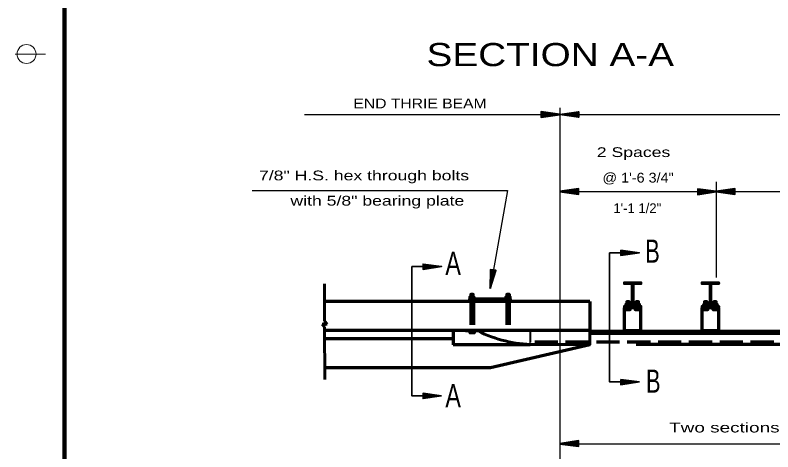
# Model space of a CAD drawing. Extents: x 856.9 to 891.7, y -2278.5 to -2254.7.
# Drawn here: x 858.05 to 868.03, y -2268.1 to -2262.35 of the extents above; entities that cross this region are included whole.
import ezdxf
from ezdxf.enums import TextEntityAlignment as Align

# ---------------------------------------------------------------- set-up
doc = ezdxf.new("R2010")
doc.units = 0
doc.header["$LTSCALE"] = 0.051
doc.linetypes.add('LONG_DASHED', pattern=[7.5, 6, -1.5])
doc.layers.add('1', color=7, linetype='Continuous', lineweight=70)
doc.layers.add('3', color=7, linetype='Continuous', lineweight=40)

msp = doc.modelspace()

# ---------------------------------------------------------------- linework, layer by layer
at = {"layer": '1', "lineweight": 25}
for p, q in [((865.22225, -2263.57275), (865.22225, -2272.82167)), ((861.86167, -2263.65783), (865.22225, -2263.65783)), ((865.22225, -2263.65783), (877.422, -2263.65783)), ((867.282, -2264.5455), (867.282, -2265.80808)), ((865.22225, -2264.67633), (877.5155, -2264.67633)), ((864.82975, -2266.6885), (864.82975, -2266.50583)), ((865.22225, -2267.99842), (873.72275, -2267.99842))]:
    msp.add_line(p, q, dxfattribs=at)
at = {"layer": '1', "lineweight": 60}
for p, q in [((862.1255, -2265.89133), (862.1255, -2266.38442)), ((864.02033, -2266.08983), (864.587, -2266.08983)), ((862.157, -2266.42175), (862.09342, -2266.42392)), ((862.09342, -2266.42392), (862.1255, -2266.45933)), ((862.1255, -2266.38442), (862.157, -2266.42175)), ((862.1255, -2266.45933), (862.12683, -2267.1535)), ((862.12625, -2266.50508), (865.61775, -2266.50508)), ((863.98108, -2266.51092), (864.14475, -2266.51092))]:
    msp.add_line(p, q, dxfattribs=at)
at = {"layer": '1'}
for p, q in [((865.61775, -2266.12317), (862.1255, -2266.12317)), ((865.61775, -2266.12317), (865.61775, -2266.50508)), ((866.07233, -2266.51742), (866.07233, -2266.20767)), ((866.29092, -2266.51742), (866.29092, -2266.20767)), ((867.09592, -2266.51742), (867.09592, -2266.20767)), ((867.31417, -2266.51742), (867.31417, -2266.20767)), ((865.61775, -2266.50508), (862.12625, -2266.50508)), ((863.81658, -2266.50508), (863.81658, -2266.69625)), ((882.07667, -2266.51742), (865.61517, -2266.51742)), ((873.06783, -2266.545), (865.61842, -2266.545)), ((863.81658, -2266.6145), (862.12625, -2266.6145)), ((864.83383, -2266.69625), (863.81658, -2266.69625)), ((865.61775, -2266.69625), (864.30783, -2266.99625)), ((882.68767, -2266.68917), (866.22875, -2266.68917)), ((864.30783, -2266.99625), (862.12625, -2266.99625))]:
    msp.add_line(p, q, dxfattribs=at)
at = {"layer": '1', "lineweight": 13}
for p, q in [((864.02033, -2266.08983), (864.02033, -2266.11992)), ((864.587, -2266.08983), (864.587, -2266.12117))]:
    msp.add_line(p, q, dxfattribs=at)
at = {"layer": '1', "linetype": 'LONG_DASHED'}
for p, q in [((864.04917, -2266.12317), (864.04917, -2266.50967)), ((864.08383, -2266.12317), (864.08383, -2266.50433)), ((873.72408, -2266.65825), (864.84167, -2266.65825))]:
    msp.add_line(p, q, dxfattribs=at)
at = {"layer": '1', "linetype": 'LONG_DASHED', "lineweight": 60}
for p, q in [((864.52333, -2266.12317), (864.52333, -2266.50633)), ((864.55875, -2266.12317), (864.55875, -2266.50108))]:
    msp.add_line(p, q, dxfattribs=at)
at = {"layer": '1', "linetype": 'LONG_DASHED', "lineweight": 13}
msp.add_line((864.84167, -2266.65825), (864.84167, -2266.50767), dxfattribs=at)
at = {"layer": '1', "lineweight": 40}
for points in [[(865.22225, -2263.65783), (864.978, -2263.6265), (864.978, -2263.69658)], [(865.22225, -2263.65783), (865.46642, -2263.62633), (865.46642, -2263.69633)], [(865.22225, -2264.67633), (865.46642, -2264.70783), (865.46642, -2264.63783)], [(867.282, -2264.67633), (867.03775, -2264.645), (867.03775, -2264.71508)], [(867.282, -2264.67633), (867.52633, -2264.70783), (867.52633, -2264.63783)], [(864.30533, -2265.95225), (864.3785, -2265.71717), (864.30983, -2265.70467)], [(865.22225, -2267.99842), (865.46658, -2268.02992), (865.46658, -2267.95992)]]:
    msp.add_lwpolyline(points, close=True, dxfattribs=at)
for points in [[(864.978, -2263.64417), (865.16125, -2263.65783), (864.978, -2263.67883)], [(864.978, -2263.65267), (865.06508, -2263.65983), (864.978, -2263.67033)], [(865.46642, -2263.644), (865.283, -2263.65783), (865.46642, -2263.67875)], [(865.46642, -2263.65242), (865.37942, -2263.65967), (865.46642, -2263.67017)], [(865.46642, -2264.69017), (865.283, -2264.67633), (865.46642, -2264.65542)], [(865.46642, -2264.68175), (865.37942, -2264.6745), (865.46642, -2264.664)], [(867.03775, -2264.66267), (867.221, -2264.67633), (867.03775, -2264.69733)], [(867.03775, -2264.67117), (867.12483, -2264.67833), (867.03775, -2264.68883)], [(867.52633, -2264.69017), (867.34292, -2264.67633), (867.52633, -2264.65542)], [(867.52633, -2264.68175), (867.43925, -2264.6745), (867.52633, -2264.664)], [(864.36167, -2265.71383), (864.31575, -2265.892), (864.32683, -2265.708)], [(864.353, -2265.71258), (864.33075, -2265.797), (864.33542, -2265.70933)], [(865.46658, -2268.01225), (865.28317, -2267.99842), (865.46658, -2267.9775)], [(865.46658, -2268.00383), (865.3795, -2267.99658), (865.46658, -2267.98608)]]:
    msp.add_lwpolyline(points, dxfattribs=at)
at = {"layer": '1', "lineweight": 25}
msp.add_lwpolyline([(861.17117, -2264.66342), (864.53175, -2264.66342), (864.30533, -2265.95225)], dxfattribs=at)
at = {"layer": '1', "lineweight": 35}
for points in [[(865.87808, -2265.48067), (866.27108, -2265.48067), (866.02692, -2265.44917), (866.02692, -2265.51925), (866.27108, -2265.48067)], [(866.02692, -2265.46683), (866.21025, -2265.48067), (866.02692, -2265.50158)], [(865.87808, -2265.48067), (865.87808, -2267.1835), (866.27108, -2267.1835)], [(866.02692, -2265.47533), (866.11392, -2265.4825), (866.02692, -2265.49308)], [(863.273, -2265.66175), (863.666, -2265.66175), (863.42175, -2265.63025), (863.42175, -2265.70033), (863.666, -2265.66175)], [(863.273, -2265.66175), (863.273, -2267.36458), (863.666, -2267.36458)], [(863.42175, -2265.64792), (863.60517, -2265.66175), (863.42175, -2265.68267)], [(863.42175, -2265.65642), (863.50892, -2265.66358), (863.42175, -2265.67417)], [(866.02692, -2267.16975), (866.21025, -2267.1835), (866.02692, -2267.2045)], [(866.02692, -2267.17825), (866.11392, -2267.18542), (866.02692, -2267.19592)], [(863.42175, -2267.35083), (863.60517, -2267.36458), (863.42175, -2267.38558)], [(863.42175, -2267.35933), (863.50892, -2267.3665), (863.42175, -2267.377)]]:
    msp.add_lwpolyline(points, dxfattribs=at)
at = {"layer": '1', "lineweight": 60}
for points in [[(866.07233, -2266.19725), (866.29092, -2266.19725), (866.29092, -2266.18658), (866.18692, -2266.18658), (866.18692, -2265.88675), (866.29092, -2265.88675), (866.29092, -2265.877), (866.07233, -2265.877), (866.07233, -2265.88675), (866.17633, -2265.88675), (866.17633, -2266.18658), (866.07233, -2266.18658)], [(867.09592, -2266.19725), (867.31417, -2266.19725), (867.31417, -2266.18658), (867.20983, -2266.18658), (867.20983, -2265.88675), (867.31417, -2265.88675), (867.31417, -2265.877), (867.09592, -2265.877), (867.09592, -2265.88675), (867.20017, -2265.88675), (867.20017, -2266.18658), (867.09592, -2266.18658)]]:
    msp.add_lwpolyline(points, close=True, dxfattribs=at)
for points in [[(864.09383, -2266.0885), (864.09383, -2266.06358), (864.03542, -2266.06358), (864.03542, -2266.0885)], [(864.08325, -2266.06358), (864.08325, -2266.02767), (864.04917, -2266.02767), (864.04917, -2266.06358)], [(864.56925, -2266.09042), (864.56925, -2266.06475), (864.51092, -2266.06475), (864.51092, -2266.09042)], [(864.55875, -2266.06558), (864.55875, -2266.02892), (864.5245, -2266.02892), (864.5245, -2266.06558)], [(866.09133, -2266.18658), (866.09133, -2266.16183), (866.14967, -2266.16183), (866.14967, -2266.18658)], [(866.10317, -2266.16183), (866.10317, -2266.12583), (866.13725, -2266.12583), (866.13725, -2266.16183)], [(866.27275, -2266.18658), (866.27275, -2266.16125), (866.21442, -2266.16125), (866.21442, -2266.18658)], [(866.26033, -2266.16183), (866.26033, -2266.12583), (866.22625, -2266.12583), (866.22625, -2266.16183)], [(867.11442, -2266.18658), (867.11442, -2266.16183), (867.17258, -2266.16183), (867.17258, -2266.18658)], [(867.12675, -2266.16183), (867.12675, -2266.12583), (867.16075, -2266.12583), (867.16075, -2266.16183)], [(867.29583, -2266.18658), (867.29583, -2266.16183), (867.23758, -2266.16183), (867.23758, -2266.18658)], [(867.28325, -2266.16183), (867.28325, -2266.12583), (867.24925, -2266.12583), (867.24925, -2266.16183)], [(866.18692, -2266.2085), (866.18692, -2266.20767), (866.29092, -2266.20767), (866.29092, -2266.19725), (866.07233, -2266.19725), (866.07233, -2266.20767), (866.18692, -2266.20767)], [(866.09133, -2266.20767), (866.09133, -2266.23267), (866.14967, -2266.23267), (866.14967, -2266.20767)], [(866.27208, -2266.20767), (866.27208, -2266.23267), (866.21383, -2266.23267), (866.21383, -2266.20767)], [(867.31417, -2266.19725), (867.09592, -2266.19725), (867.09592, -2266.20767), (867.31417, -2266.20767)], [(867.11442, -2266.20767), (867.11442, -2266.23267), (867.17258, -2266.23267), (867.17258, -2266.20767)], [(867.29583, -2266.20767), (867.29583, -2266.23267), (867.23758, -2266.23267), (867.23758, -2266.20767)], [(864.03933, -2266.51292), (864.03933, -2266.53767), (864.09692, -2266.53767), (864.09692, -2266.51292)], [(864.88167, -2266.68917), (865.61775, -2266.68917), (865.61775, -2266.50508)], [(866.18692, -2266.50767), (866.07233, -2266.50767), (866.07233, -2266.51742)], [(866.07233, -2266.51742), (866.29092, -2266.51742), (866.29092, -2266.50767), (866.18692, -2266.50767)], [(867.09592, -2266.51742), (867.31417, -2266.51742), (867.31417, -2266.50767), (867.20983, -2266.50767)], [(867.20983, -2266.50767), (867.09592, -2266.50767), (867.09592, -2266.51742)]]:
    msp.add_lwpolyline(points, dxfattribs=at)
at = {"layer": '1', "lineweight": 35}
for points in [[(866.27108, -2267.1835), (866.02692, -2267.15217), (866.02692, -2267.22217)], [(863.666, -2267.36458), (863.42175, -2267.33325), (863.42175, -2267.40325)]]:
    msp.add_lwpolyline(points, close=True, dxfattribs=at)
at = {"layer": '1', "lineweight": 60}
msp.add_ellipse((864.8815, -2265.02141), major_axis=(0, -1.66797), ratio=0.9817, start_param=5.8167029, end_param=6.2831853, dxfattribs=at)
at = {"layer": '3', "lineweight": 158}
msp.add_line((858.7, -2256.16333), (858.7, -2277.16333), dxfattribs=at)
at = {"layer": '3', "lineweight": 13}
msp.add_line((858.45, -2262.86333), (858.05, -2262.86333), dxfattribs=at)
msp.add_circle((858.2, -2262.86333), 0.125, dxfattribs=at)

# ---------------------------------------------------------------- texts
at = {"layer": '1'}
for s, width, p in [('SECTION A-A', 1.25, (865.09663, -2263.023)), ('B', 0.7, (866.44275, -2265.61283)), ('A', 0.75, (863.81742, -2265.7735)), ('B', 0.7, (866.45292, -2267.32575)), ('A', 0.75, (863.81733, -2267.51708))]:
    msp.add_text(s, height=0.3052, dxfattribs=dict(at, width=width)).set_placement(p, align=Align.CENTER)
for s, width, p in [('END THRIE BEAM', 1.2, (862.50408, -2263.57892)), ('2 Spaces', 1.35, (865.70925, -2264.22042)), ('7/8" H.S. hex through bolts', 1.35, (861.26075, -2264.52767)), ('@ 1\'-6 3/4"', 1.1, (865.78458, -2264.5565)), ('with 5/8" bearing plate', 1.35, (861.67483, -2264.86017)), ('Two sections of thrie beam', 1.45, (866.6615, -2267.84917))]:
    msp.add_text(s, height=0.1286, dxfattribs=dict(at, width=width)).set_placement(p)
msp.add_text('1\'-1 1/2"', height=0.1286, dxfattribs=at).set_placement((865.92808, -2264.95867))

doc.saveas('drawing.dxf')
